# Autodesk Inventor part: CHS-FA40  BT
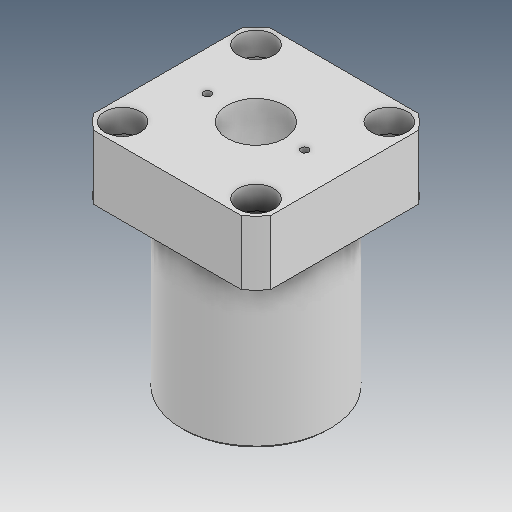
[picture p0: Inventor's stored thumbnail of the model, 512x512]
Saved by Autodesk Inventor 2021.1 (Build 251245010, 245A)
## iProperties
Created: 2019-04
Part Number: CHS-FA40  BT
Material: Ogólny
Document SubType Name: Modeling
Designer: user
Density: 1 g/cm^3
Appearance: Domyślna
Author: user
Revision Number: ÈÎºÎ
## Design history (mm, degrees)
feature "ÊäÈë1"
node "Bryła1"
